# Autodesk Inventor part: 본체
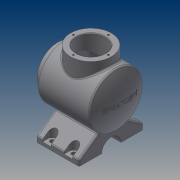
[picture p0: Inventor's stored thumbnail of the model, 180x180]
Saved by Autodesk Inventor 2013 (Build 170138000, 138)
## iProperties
Created: 2017-04
Part Number: 본체
Material: 일반
Document SubType Name: Modeling
Designer: Windows7
Density: 1 g/cm^3
Author: Windows7
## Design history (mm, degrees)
sketch "스케치3"
  geometry: L1 (-54, 0)-(54, 0); L2 (-54, 0)-(-54, 50); L3 (-54, 50)-(42.336, 50); L4 (35.916, 40)-(-44, 40); L5 (-44, 40)-(-44, 0); A1 r 113 centre (-59, 0) between (54, 0) and (42.336, 50); A2 r 103 centre (-59, 0) between (44, 0) and (35.916, 40); 2 further points
  constraints: 10 end point, 4 point on circle, 3 perpendicular, 2 centre point, 2 point on line, 1 coincident, 1 horizontal, 1 horizontal alignment, 1 midpoint
  dimensions: "d13" = 113 radius of A1; "d14" = 100 diameter of L3 L1; "d15" = 10 distance between parallel lines of L5 L2; "d16" = 10 radial gap between concentric circles of A1 A2; "d17" = 10 distance between parallel lines of L4 L3; "d143" = 108 horizontal distance of L1.end L2.end
revolve "회전2" sketch "스케치3" stored, may be unused: angle "d18" = 90 deg
sketch "스케치4"
  geometry: C1 r 50 at (0, 0) reference; C2 r 38 at (0, 0)
  constraints: 1 centre point, 1 coincident
  dimensions: "d19" = 76 diameter of C2
extrude "돌출1" join sketch "스케치4" distance "d20" = 12; taper "d21" = 0 deg
sketch "스케치5"
  geometry: C1 r 38 at (0, 0) reference; C2 r 27 at (0, 0)
  constraints: 1 centre point, 1 coincident
  dimensions: "d22" = 54 diameter of C2
extrude "돌출2" cut sketch "스케치5" distance "d23" = 50; taper "d24" = 0 deg
node "작업 평면2"
sketch "스케치7"
  geometry: L1 (-34, 60)-(46, 60); L2 (46, 60)-(46, -60); L3 (46, -60)-(-34, -60); L4 (-34, -60)-(-34, 60); L5 (54, 50)-(54, -50) reference; 2 further points
  constraints: 8 end point, 2 parallel, 1 horizontal, 1 horizontal alignment, 1 midpoint, 1 perpendicular
  dimensions: "d30" = 8 distance from line of L2.end L5; "d31" = 80 distance of L2.end L3.end; "d32" = 120 distance of L3.end L1.start
extrude "돌출3" join sketch "스케치7" distance "d33" = 10; taper "d34" = 0 deg
sketch "스케치10"
  geometry: L1 (34, -60)-(34, 60) reference; L2 (-46, 60)-(-46, -60) reference; L3 (-46, 5)-(34, 5); L4 (34, 5)-(34, -5); L5 (34, -5)-(-46, -5); L6 (-46, -5)-(-46, 5); 2 further points
  constraints: 8 end point, 2 parallel, 2 point on line, 1 horizontal, 1 horizontal alignment, 1 midpoint, 1 perpendicular
  dimensions: "d35" = 10 distance of L3.end L4.end
extrude "돌출4" join sketch "스케치10" stored distance "d37" = 10; taper "d38" = 0 deg
node "작업 평면3"
sketch "스케치11"
  geometry: L1 (55, 10)-(55, 32.251) reference; L2 (65, 32.251)-(65, 10) reference; L3 (65, 10)-(120, 10) reference; L4 (120, 10)-(120, 0) reference; L5 (120, 0)-(0, 0) reference; L6 (0, 0)-(0, 10) reference; L7 (0, 10)-(55, 10) reference; L8 (0, 10)-(38.416, 36.899); L9 (120, 10)-(81.584, 36.899); C1 r 40 at (60, 82) reference; A1 r 50 centre (60, 82) between (65, 32.251) and (55, 32.251) reference; 1 further point
  constraints: 4 end point, 2 point on circle
  dimensions: "d40" = 55 deg angle of L8 L6; "d41" = 55 deg angle of L9 L4
  node "절단 모서리 투영4"
feature "리브1" dims "d42" = 1, "d43" = 80, "d44" = 0, "d45" = 0, "d46" = 1, "d47" = 1
feature "리브2" dims "d48" = 1, "d49" = 80, "d50" = 0, "d51" = 0, "d52" = 1, "d53" = 1
sketch "스케치12"
  geometry: L1 (120, 0)-(0, 0) reference; C1 r 18 at (60, 0); A1 r 50 centre (60, 82) between (38.416, 36.899) and (81.584, 36.899) reference
  constraints: 1 centre point, 1 midpoint, 1 vertical alignment
  dimensions: "d54" = 36 diameter of C1
extrude "돌출5" cut sketch "스케치12" distance "d56" = 80; taper "d57" = 0 deg
node "작업 평면4"
sketch "스케치13"
  geometry: L1 (-54, -50)-(-54, 50) reference; C1 r 38 at (-4, 0); 1 further point
  constraints: 1 centre point, 1 horizontal alignment
  dimensions: "d121" = 76 diameter of C1; "d123" = 50 distance from line of C1.centre L1
extrude "돌출6" join sketch "스케치13" stored distance "d60" = 80; taper "d61" = 0 deg
sketch "스케치15"
  geometry: L1 (-46, 60)-(-46, 18) reference; C1 r 4 at (-26, 50); 1 further point
  constraints: 1 centre point
  dimensions: "d65" = 8 diameter of C1; "d67" = 50 vertical distance of point (0, 0) C1.centre; "d76" = 20 distance from line of C1.centre L1
extrude "돌출8" cut sketch "스케치15" distance "d69" = 6; taper "d70" = 0 deg
sketch "스케치16"
  geometry: L1 (-8, 0)-(-8, 10); L2 (8, 0)-(8, 10); L3 (-8, 10)-(8, 10); C1 r 4 at (0, 0) reference; A1 r 8 centre (0, 0) between (-8, 0) and (8, 0); 1 further point
  constraints: 6 end point, 2 point on circle, 2 tangent, 1 centre point, 1 coincident, 1 parallel, 1 vertical
  dimensions: "d71" = 8 radius of A1; "d72" = 10 distance of L1.start L1.end; "d73" = 10 distance of L2.start L2.end
extrude "돌출9" cut sketch "스케치16" distance "d74" = 20; taper "d75" = 0 deg
sketch "스케치17" dims "d83" = 65
  geometry: L1 (0, 0)-(0, 32.5); C1 r 38 at (0, 0) reference
  constraints: 2 end point, 1 coincident, 1 vertical, 1 vertical alignment, 2 other
hole "구멍1" sketch "스케치17" at (0, 32.5) diameter "d84" = 3.242; stored, may be unused: countersink angle "d88" = 90 deg, drill point angle "d90" = 120 deg; dims "d85" = 8, "d86" = 4, "d87" = 2, "d89" = 10
node "작업 평면5"
sketch "스케치19"
  geometry: 2 further points
  constraints: 1 coincident, 1 other
feature "엠보싱1" sketch "스케치19" dims "d22" = 54, "d105" = 0.5, "d106" = 0
fillet "모깎기1" dims "d107" = 3
fillet "모깎기2" dims "d108" = 3
fillet "모깎기3" dims "d112" = 3
chamfer "모따기1" distance "d113" = 1; stored, may be unused: second distance "d114" = 2, angle "d115" = 45 deg
fillet "모깎기4" dims "d120" = 3
sketch "스케치20"
  geometry: C1 r 38 at (0, 0) reference; C2 r 27 at (0, 0); 1 further point
  constraints: 1 centre point, 1 coincident
  dimensions: "d124" = 54 diameter of C2
extrude "돌출10" cut sketch "스케치20" distance "d125" = 50; taper "d126" = 0 deg
sketch "스케치21" dims "d127" = 65
  geometry: L1 (0, 0)-(0, 32.5); C1 r 27 at (0, 0) reference; C2 r 38 at (0, 0) reference; 1 further point
  constraints: 2 end point, 2 vertical alignment, 1 coincident, 2 other
hole "구멍3" sketch "스케치21" at (0, 32.5) diameter "d128" = 3.242; stored, may be unused: countersink angle "d132" = 90 deg, drill point angle "d134" = 120 deg; dims "d129" = 8, "d130" = 4, "d131" = 2, "d133" = 10
chamfer "모따기2" distance "d138" = 1; stored, may be unused: second distance "d139" = 2, angle "d140" = 45 deg
fillet "모깎기5" dims "d141" = 3
node "솔리드2"
pattern_circular "원형 패턴1" dims angle "d92" = 360 deg
pattern_linear "직사각형 패턴2"
mirror "대칭1"
pattern_circular "원형 패턴4" dims angle "d145" = 360 deg
other parameters: "d29" = -82, "d58" = -147, "d116" = 0.5, "d117" = 2, "d118" = 0
